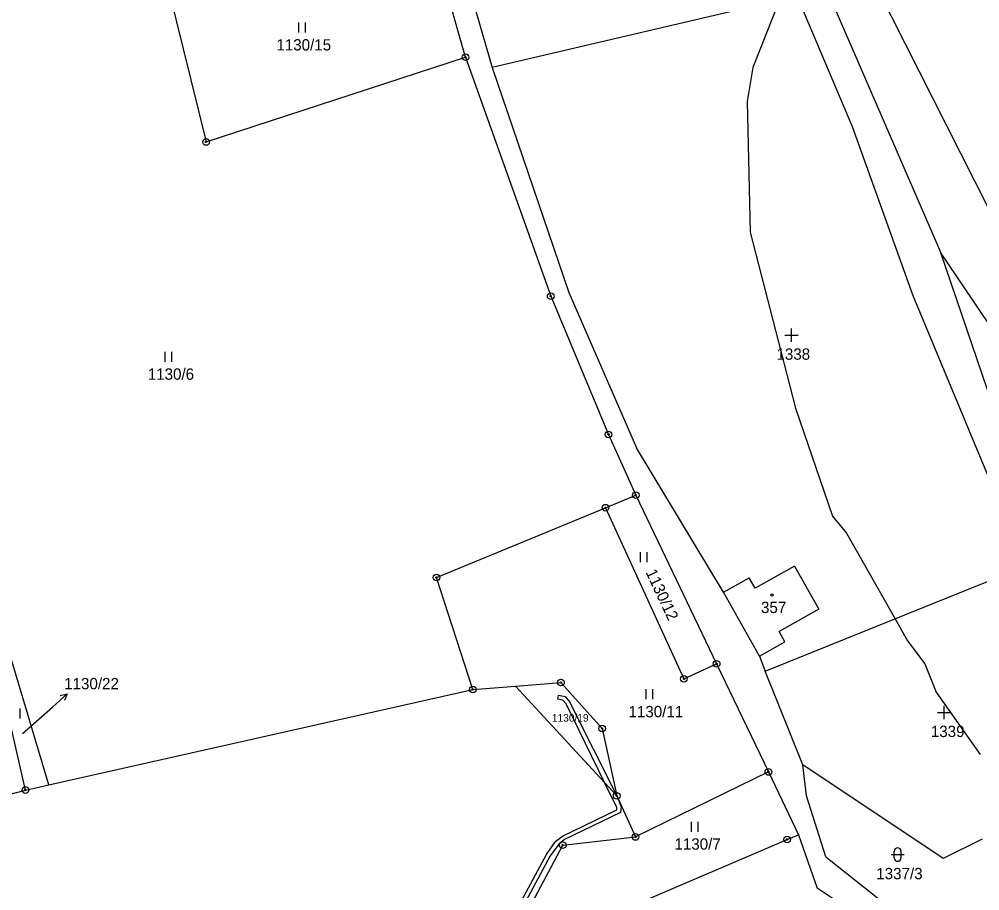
# Model space of a CAD drawing. Extents: x -439246 to -433691, y -1130252 to -1121148.
# Drawn here: x -437967.4 to -437823.2, y -1123969.1 to -1123838.4 of the extents above; entities that cross this region are included whole.
import ezdxf

# ---------------------------------------------------------------- set-up
doc = ezdxf.new("R2010")
doc.units = 0
for name, color, linetype in [('Vrstva 1', 7, 'Continuous'), ('Vrstva 16', 7, 'Continuous'), ('Vrstva 18', 7, 'Continuous'), ('Vrstva 19', 7, 'Continuous'), ('Vrstva 24', 7, 'Continuous'), ('Vrstva 25', 7, 'Continuous'), ('Vrstva 3', 7, 'Continuous'), ('Vrstva 30', 7, 'Continuous'), ('Vrstva 37', 7, 'Continuous'), ('Vrstva 52', 7, 'Continuous'), ('Vrstva 6', 7, 'Continuous')]:
    doc.layers.add(name, color=color, linetype=linetype)

msp = doc.modelspace()

# ---------------------------------------------------------------- linework, layer by layer
at = {"layer": 'Vrstva 1'}
for p, q in [((-437962.92, -1123953.24), (-437978.75, -1123900.28)), ((-437962.92, -1123953.24), (-437899.29, -1123938.94)), ((-437966.42, -1123954.03), (-437962.92, -1123953.24)), ((-437885.79, -1123962.29), (-437874.86, -1123961.07)), ((-437875.48, -1123971.44), (-437852.11, -1123961.44)), ((-437893.15, -1123976.13), (-437885.79, -1123962.29))]:
    msp.add_line(p, q, dxfattribs=at)
for points in [[(-437900.38, -1123844.04), (-437911.95, -1123803.46)], [(-437907.77, -1123806.25), (-437896.36, -1123845.62)], [(-437849.05, -1123813.02), (-437815.62, -1123879.14)], [(-437949.56, -1123815.23), (-437939.31, -1123856.78)], [(-437846.41, -1123833.35), (-437829.04, -1123873.39)], [(-437850.58, -1123834.83), (-437896.36, -1123845.62)], [(-437842.3, -1123854.49), (-437850.58, -1123834.83)], [(-437939.31, -1123856.78), (-437900.38, -1123844.04)], [(-437900.38, -1123844.04), (-437887.59, -1123879.92)], [(-437896.36, -1123845.62), (-437884.85, -1123879.39)], [(-437833.2, -1123879.86), (-437842.3, -1123854.49)], [(-437807.51, -1123905.21), (-437829.04, -1123873.39)], [(-437815.02, -1123914.55), (-437829.04, -1123873.39)], [(-437887.59, -1123879.92), (-437878.91, -1123900.67)], [(-437884.85, -1123879.39), (-437874.7, -1123902.67)], [(-437817.81, -1123916.86), (-437833.2, -1123879.86)], [(-437878.91, -1123900.67), (-437874.82, -1123909.78)], [(-437861.64, -1123924.32), (-437874.7, -1123902.67)], [(-437879.37, -1123911.66), (-437874.82, -1123909.78)], [(-437874.82, -1123909.78), (-437862.69, -1123935.1)], [(-437904.74, -1123922.14), (-437879.37, -1123911.66)], [(-437879.37, -1123911.66), (-437867.6, -1123937.35)], [(-437850.98, -1123920.44), (-437856.92, -1123923.75)], [(-437855.41, -1123936.2), (-437816.33, -1123920.43)], [(-437850.98, -1123920.44), (-437847.37, -1123926.9)], [(-437899.29, -1123938.94), (-437904.74, -1123922.14)], [(-437861.64, -1123924.32), (-437857.8, -1123922.18)], [(-437856.92, -1123923.75), (-437857.8, -1123922.18)], [(-437856.28, -1123933.93), (-437861.64, -1123924.32)], [(-437966.42, -1123954.03), (-437973.12, -1123924.83)], [(-437847.37, -1123926.9), (-437853.31, -1123930.22)], [(-437852.44, -1123931.79), (-437853.31, -1123930.22)], [(-437856.28, -1123933.93), (-437852.44, -1123931.79)], [(-437856.28, -1123933.93), (-437855.41, -1123936.2)], [(-437867.6, -1123937.35), (-437862.69, -1123935.1)], [(-437862.69, -1123935.1), (-437854.92, -1123951.32)], [(-437849.74, -1123950.26), (-437855.41, -1123936.2)], [(-437899.29, -1123938.94), (-437892.87, -1123938.43)], [(-437892.87, -1123938.43), (-437886.05, -1123937.89)], [(-437879.87, -1123944.81), (-437886.05, -1123937.89)], [(-437879.87, -1123944.81), (-437877.69, -1123954.9)], [(-437828.67, -1123964.32), (-437849.74, -1123950.26)], [(-437849.2, -1123954.92), (-437849.74, -1123950.26)], [(-437854.92, -1123951.32), (-437874.86, -1123961.07)], [(-437854.92, -1123951.32), (-437850.42, -1123960.73)], [(-437985.43, -1123958.96), (-437966.42, -1123954.03)], [(-437877.69, -1123954.9), (-437874.86, -1123961.07)], [(-437846.28, -1123964.03), (-437849.2, -1123954.92)], [(-437852.11, -1123961.44), (-437850.42, -1123960.73)], [(-437850.42, -1123960.73), (-437847.59, -1123968.74)], [(-437822.82, -1123961.42), (-437828.67, -1123964.32)], [(-437846.28, -1123964.03), (-437837.59, -1123970.97)], [(-437840.83, -1123973.26), (-437847.59, -1123968.74)]]:
    msp.add_lwpolyline(points, dxfattribs=at)
at = {"layer": 'Vrstva 16'}
msp.add_line((-437962.38, -1123941.57), (-437960.14, -1123939.57), dxfattribs=at)
for points in [[(-437961.22, -1123939.86), (-437960.14, -1123939.57), (-437960.56, -1123940.61)], [(-437966.84, -1123945.56), (-437962.38, -1123941.57)]]:
    msp.add_lwpolyline(points, dxfattribs=at)
at = {"layer": 'Vrstva 24'}
for centre, radius in [((-437900.38, -1123844.04), 0.5), ((-437900.38, -1123844.04), 0.1), ((-437939.31, -1123856.78), 0.5), ((-437939.31, -1123856.78), 0.1), ((-437887.59, -1123879.92), 0.5), ((-437887.59, -1123879.92), 0.1), ((-437878.91, -1123900.67), 0.5), ((-437878.91, -1123900.67), 0.1), ((-437874.82, -1123909.78), 0.5), ((-437874.82, -1123909.78), 0.1), ((-437879.37, -1123911.66), 0.5), ((-437879.37, -1123911.66), 0.1), ((-437904.74, -1123922.14), 0.5), ((-437904.74, -1123922.14), 0.1), ((-437862.69, -1123935.1), 0.5), ((-437862.69, -1123935.1), 0.1), ((-437886.05, -1123937.89), 0.5), ((-437867.6, -1123937.35), 0.5), ((-437867.6, -1123937.35), 0.1), ((-437899.29, -1123938.94), 0.5), ((-437899.29, -1123938.94), 0.1), ((-437886.05, -1123937.89), 0.1), ((-437879.87, -1123944.81), 0.5), ((-437879.87, -1123944.81), 0.1), ((-437854.92, -1123951.32), 0.5), ((-437854.92, -1123951.32), 0.1), ((-437966.42, -1123954.03), 0.5), ((-437966.42, -1123954.03), 0.1), ((-437877.69, -1123954.9), 0.5), ((-437877.69, -1123954.9), 0.1), ((-437874.86, -1123961.07), 0.5), ((-437885.79, -1123962.29), 0.5), ((-437874.86, -1123961.07), 0.1), ((-437852.11, -1123961.44), 0.5), ((-437852.11, -1123961.44), 0.1), ((-437885.79, -1123962.29), 0.1)]:
    msp.add_circle(centre, radius, dxfattribs=at)
at = {"layer": 'Vrstva 25'}
for p, q in [((-437925.38, -1123840.35), (-437925.38, -1123838.85)), ((-437924.38, -1123840.35), (-437924.38, -1123838.85)), ((-437852.43, -1123885.76), (-437850.43, -1123885.76)), ((-437851.43, -1123886.76), (-437851.43, -1123884.76)), ((-437945.46, -1123889.76), (-437945.46, -1123888.26)), ((-437944.46, -1123889.76), (-437944.46, -1123888.26)), ((-437874.09, -1123919.83), (-437874.09, -1123918.33)), ((-437873.09, -1123919.83), (-437873.09, -1123918.33)), ((-437873.24, -1123940.41), (-437873.24, -1123938.91)), ((-437872.24, -1123940.41), (-437872.24, -1123938.91)), ((-437967.23, -1123943.29), (-437967.23, -1123941.79)), ((-437828.55, -1123943.38), (-437828.55, -1123941.38)), ((-437829.55, -1123942.38), (-437827.55, -1123942.38)), ((-437866.45, -1123960.28), (-437866.45, -1123958.78)), ((-437865.45, -1123960.28), (-437865.45, -1123958.78)), ((-437836.02, -1123964.22), (-437836.02, -1123963.22)), ((-437835.02, -1123963.22), (-437835.02, -1123964.22)), ((-437836.52, -1123963.72), (-437834.52, -1123963.72))]:
    msp.add_line(p, q, dxfattribs=at)
msp.add_circle((-437854.4, -1123924.77), 0.175, dxfattribs=at)
for centre, start, end in [((-437835.52, -1123963.22), 0, 180), ((-437835.52, -1123964.22), 180, 0)]:
    msp.add_arc(centre, 0.5, start, end, dxfattribs=at)
at = {"layer": 'Vrstva 3'}
for points in [[(-437850.98, -1123920.44), (-437856.92, -1123923.75)], [(-437850.98, -1123920.44), (-437847.37, -1123926.9)], [(-437861.64, -1123924.32), (-437857.8, -1123922.18)], [(-437856.92, -1123923.75), (-437857.8, -1123922.18)], [(-437856.28, -1123933.93), (-437861.64, -1123924.32)], [(-437847.37, -1123926.9), (-437853.31, -1123930.22)], [(-437852.44, -1123931.79), (-437853.31, -1123930.22)], [(-437856.28, -1123933.93), (-437852.44, -1123931.79)]]:
    msp.add_lwpolyline(points, dxfattribs=at)
at = {"layer": 'Vrstva 30'}
for points in [[(-437893.67, -1123973.8), (-437888.16, -1123963.58), (-437886.81, -1123961.71), (-437885.83, -1123960.93), (-437877.68, -1123957.01), (-437877.66, -1123956.65), (-437879.46, -1123952.98), (-437885.28, -1123941.11), (-437885.75, -1123940.54), (-437886.54, -1123940.38)], [(-437886.54, -1123940.38), (-437886.42, -1123939.8), (-437885.41, -1123940), (-437884.78, -1123940.79), (-437877.69, -1123954.9), (-437877.04, -1123956.53), (-437877.11, -1123957.4)], [(-437877.11, -1123957.4), (-437885.51, -1123961.44), (-437886.37, -1123962.13), (-437887.66, -1123963.9), (-437893.17, -1123974.14)]]:
    msp.add_lwpolyline(points, dxfattribs=at)
at = {"layer": 'Vrstva 37'}
msp.add_circle((-437854.4, -1123924.77), 0.175, dxfattribs=at)
at = {"layer": 'Vrstva 52'}
msp.add_lwpolyline([(-437822.52, -1123799.13), (-437830.19, -1123809.36), (-437843.52, -1123823.96), (-437848.49, -1123829.41), (-437850.21, -1123831.3), (-437851.53, -1123833.09), (-437853.2, -1123835.35), (-437853.24, -1123835.46), (-437857.25, -1123845.58), (-437858.1, -1123850.69), (-437857.67, -1123870.3), (-437850.85, -1123896.72), (-437845.32, -1123912.91), (-437844.83, -1123913.5), (-437843.18, -1123915.47), (-437835.91, -1123928.33), (-437834.02, -1123931.66), (-437831.46, -1123935.07), (-437829.76, -1123939.33), (-437823.16, -1123948.71)], dxfattribs=at)
at = {"layer": 'Vrstva 6'}
msp.add_lwpolyline([(-437877.69, -1123954.9), (-437892.87, -1123938.43)], dxfattribs=at)

# ---------------------------------------------------------------- texts
at = {"layer": 'Vrstva 16'}
msp.add_text('1130/22', height=1.7, dxfattribs=at).set_placement((-437960.61, -1123938.91))
at = {"layer": 'Vrstva 18'}
for s, height, p in [('1130/15', 1.7, (-437928.76, -1123843.05)), ('1338', 1.7, (-437853.71, -1123889.46)), ('1130/6', 1.7, (-437948.06, -1123892.46)), ('1130/11', 1.7, (-437875.92, -1123943.11)), ('1130/19', 1.14, (-437887.41, -1123943.77)), ('1339', 1.7, (-437830.54, -1123946.08)), ('1130/22', 0.1, (-437966.84, -1123945.56)), ('1130/7', 1.7, (-437869.02, -1123962.98)), ('1337/3', 1.7, (-437838.73, -1123967.42))]:
    msp.add_text(s, height=height, dxfattribs=at).set_placement(p)
msp.add_text('1130/12', height=1.7, rotation=295.1417, dxfattribs=at).set_placement((-437873.38, -1123921.34))
at = {"layer": 'Vrstva 19'}
msp.add_text('357', height=1.7, dxfattribs=at).set_placement((-437856.03, -1123927.47))

doc.saveas('drawing.dxf')
